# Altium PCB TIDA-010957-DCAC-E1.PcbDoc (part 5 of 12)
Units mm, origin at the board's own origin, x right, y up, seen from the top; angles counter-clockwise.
Board outline 300 x 300 mm, 4 copper layers (Top Layer, Layer 1, Layer 2, Bottom Layer), stack 1.787 mm thick; 1159 components, 619 nets, 3431 pads, 2942 vias.
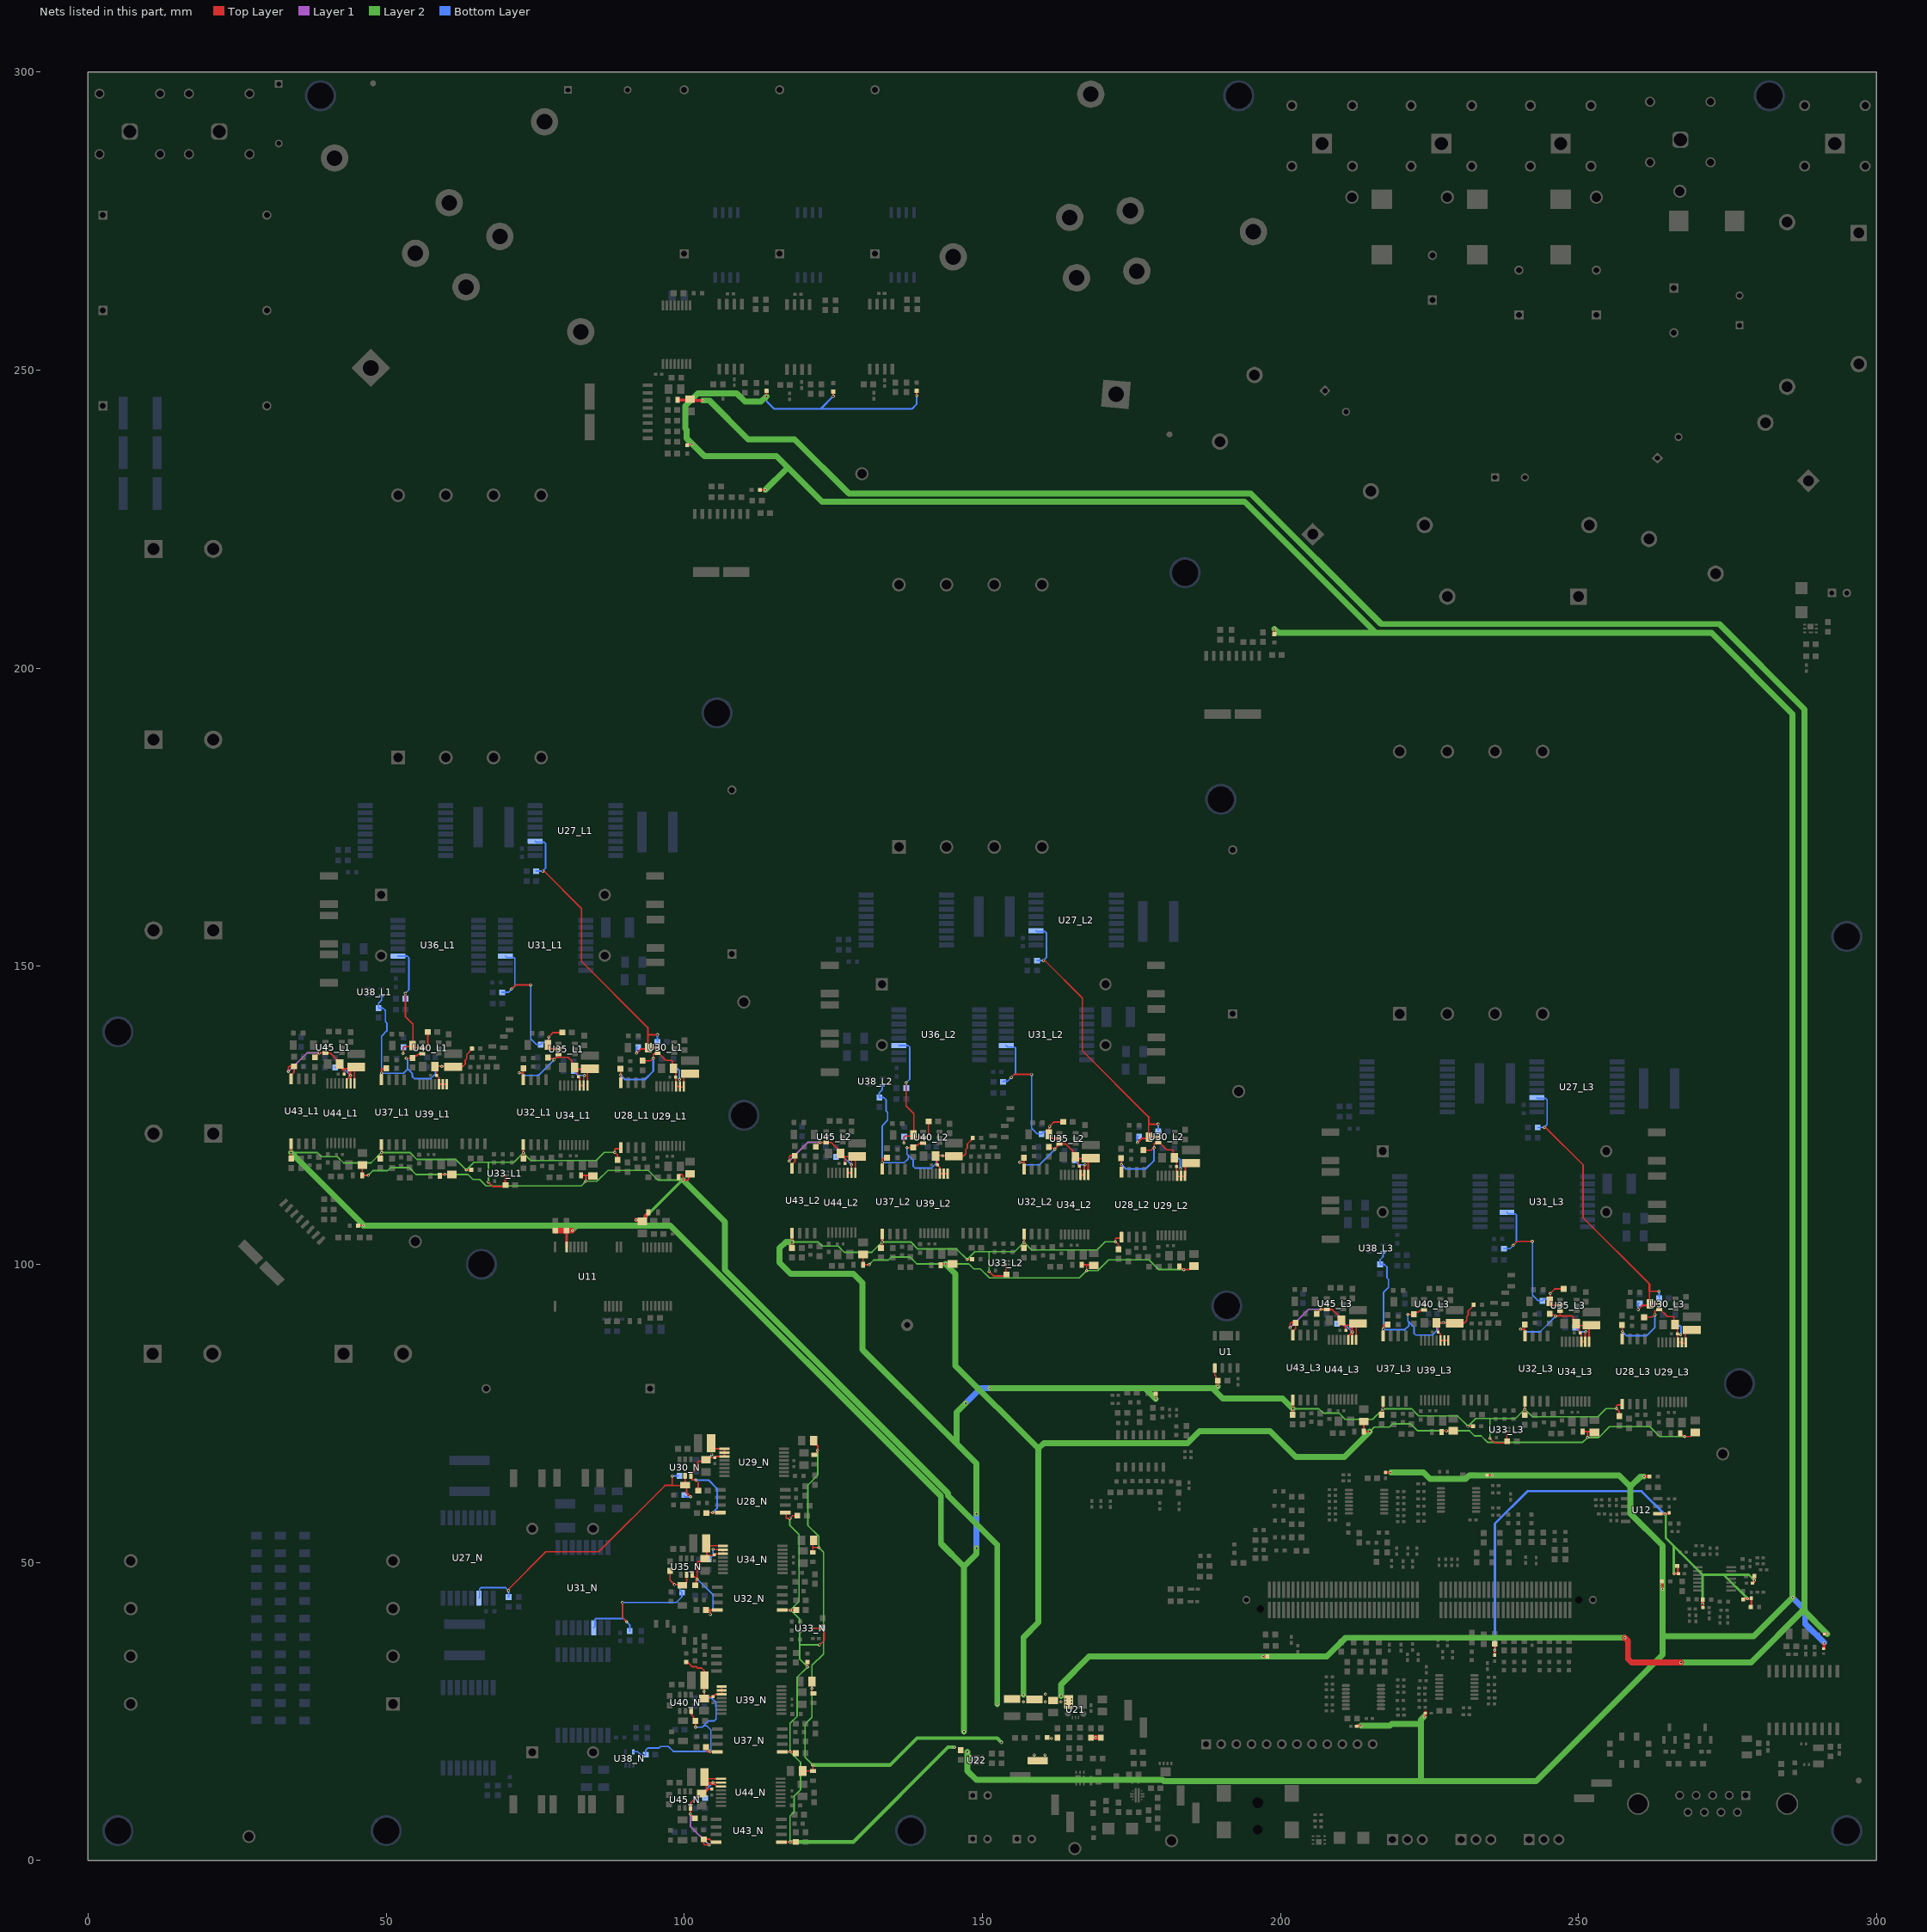
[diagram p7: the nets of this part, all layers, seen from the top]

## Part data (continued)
R290_L1 R290_L2 R290_L3 R290_N R301_L1 R301_L2 R301_L3 R301_N R311_L1 R311_L2 R311_L3 R311_N R328_L1 R328_L2 R328_L3 R328_N: library part CMP-0023259-5, "RES, 71.5 k, 1%, 0.1 W, 0603", Manufacturer=Yageo, Power_W=100mW, Supplier Part Number 1=311-71.5KHRCT-ND, TempCo="100 ppm/C", Tolerance_%=1%, Value2=0.1W, Value_Code=71k5, ValueDisplayed=71.5k
R312_L1 R312_L2 R312_L3 R312_N R313_L1 R313_L2 R313_L3 R313_N R314_L1 R314_L2 R314_L3 R314_N: library part CMP-0124370-1, "680 kOhms ±0.1% 0.2W, 1/5W Chip Resistor 0805 (2012 Metric) Anti-Sulfur, Automotive AEC-Q200, High Voltage, Moisture Resistant Thin Film", Digikey Part Number=541-TNPV0805680KBEEACT-ND, Manufacturer=Vishay, Mouser Part Number=71-TNPV0805680KBEEA, Operating Temperature Range="-55°C to +125°C", Power_W=200mW, TempCo=25ppm/°C, Tolerance_%=0.1%
R315_L1 R315_L2 R315_L3 R315_N: library part CMP-0122747-1, "8 kOhms ±0.1% 0.1W, 1/10W Chip Resistor 0603 (1608 Metric) Thin Film", Digikey Part Number=13-RT0603BRE078KLCT-ND, Manufacturer=Yageo, Mouser Part Number=603-RT0603BRE078KL, Operating Temperature Range="-55°C to +155°C", Power_W=100mW, TempCo=50ppm/°C, Tolerance_%=0.1%
R329: library part CMP-0026874-3, "RES, 200, 5%, 0.063 W, AEC-Q200 Grade 0, 0402", Manufacturer=Vishay-Dale, Power_W=63mW, Supplier Part Number 1=541-200JCT-ND, TempCo="200 ppm/C", Tolerance_%=5%, Value2=0.063W, Value_Code=200R, ValueDisplayed=200
RN1 RN2 RN3: library part CMP-0122946-1, "Automotive, 1700-V, Precision Resistive Divider", Manufacturer="Texas Instruments", Number Of Resistors=2, Operating Temperature Range="-40°C to +125°C", TempCo=1ppm/°C, Tolerance_%=0.05%
TP1: library part CMP-0055138-2, "Test Point, Miniature, Black, TH", Color=Black, Manufacturer="Keystone Electronics", Supplier Part Number 1=36-5001-ND
TP2 TP3 TP4 TP6 TP7 TP8 TP9 TP10 TP11 TP12 TP13: library part CMP-0055148-2, "Test Point, Multipurpose, Black, TH", Color=Black, Manufacturer="Keystone Electronics", Supplier Part Number 1=36-5011-ND
TP5: library part CMP-0055147-2, "Test Point, Multipurpose, Red, TH", Color=Red, Manufacturer="Keystone Electronics", Supplier Part Number 1=36-5010-ND
U1: library part CMP-0122473-1, "Automotive ±1.5°C, 3-kVRMS Isolated Temperature Sensor With Analog Output With < 2 Seconds Response Time and 500VRMS Working Voltage", Manufacturer="Texas Instruments", Max Supply Voltage=5.5V, Min Supply Voltage=2.3V, Operating Supply Current=10uA, Operating Temperature Range="-40°C to +150°C"
U2 U4 U5 U6: library part CMP-0097958-1, Manufacturer="Texas Instruments", Operating Temperature Range=to
U3: library part CMP-0121217-1, "Zero-Drift Amplifier 4 Circuit Rail-to-Rail 14-TSSOP", Digikey Part Number=296-OPA4388IPWRCT-ND, Input Bias Current=0.00003uA, Input Offset Voltage=0.00225mV, Manufacturer="Texas Instruments", Max Dual Supply Voltage=2.75V, Max Supply Voltage=5.5V, Min Dual Supply Voltage=1.25V, Min Supply Voltage=2.5V, Mouser Part Number=595-OPA4388IPWR, Nominal Supply Current=1.7-1.9mA, Operating Temperature Range="-40°C to +125°C", Output Current Per Channel=60mA, Voltage Gain=126dB
U7 U8 U9: library part CMP-0122725-1, "Automotive, Precision, ±1V Input Isolated Amplifiers With Single-Ended, Ratiometric Output", Input Bias Current=0.0035uA, Input Offset Voltage=0.4mV, Manufacturer="Texas Instruments", Max Supply Voltage=5.5V, Min Supply Voltage=3V, Operating Temperature Range="-40°C to +125°C", Output Current Per Channel=14mA
U10 U13: library part CMP-0123146-1, "Ultra-Small, 1.5W, 5.0V, 5kVRMS Isolation, Industrial DC/DC Module", Manufacturer="Texas Instruments", Max Supply Voltage=5.5V, Min Supply Voltage=4.5V, Nominal Supply Current=7-545mA, Operating Temperature Range="-40°C to +125°C", Output Voltage=5/5.5V, Switching Frequency=76MHz
U11: library part CMP-0044881-2, Manufacturer="Texas Instruments", Operating Temperature Range=to
U12: library part CMP-0121707-1, "Precision, Low-Offset-Voltage, Low-Noise, Low-Input-Bias-Current, Rail-to-Rail I/O, e-trim™ Operational Amplifiers", Digikey Part Number=296-OPA2392DRCT-ND, Input Bias Current=0.00000001uA, Input Offset Voltage=0.001mV, Manufacturer="Texas Instruments", Max Dual Supply Voltage=2.75V, Max Supply Voltage=5.5V, Min Dual Supply Voltage=850mV, Min Supply Voltage=1.7V, Mouser Part Number=595-OPA2392DR, Nominal Supply Current=1.22mA, Operating Temperature Range="-40°C to +125°C", Output Current Per Channel=65mA, Voltage Gain=132dB
U14: library part CMP-0097120-1, "Op Amp Quad Zero Drift Amplifier R-R I/O ±2.75V/5.5V 14-Pin SOIC T/R", Digikey Part Number=296-53511-1-ND, Input Bias Current=0.00003uA, Input Offset Voltage=0.00225mV, Manufacturer="Texas Instruments", Max Dual Supply Voltage=2.75V, Max Supply Voltage=5.5V, Min Dual Supply Voltage=1.25V, Min Supply Voltage=2.5V, Mouser Part Number=595-OPA4388IDR, Nominal Supply Current=1.7-1.9mA, Operating Temperature Range="-40°C to +125°C", Output Current Per Channel=60mA, Voltage Gain=148dB
U15 U16 U17 U18: library part CMP-0066280-1, "Quadruple Bus Buffer Gate with 3-State Outputs, PW0014A (TSSOP-14)", Alternate Manufacturer="Texas Instruments", Alternate PartNumber=SN74LVC126APW
U19: library part CMP-0088329-1, "2.7- 23V, 5.5 A, 28 mΩ Reverse Current Blocking eFuse with Input Reverse Polarity Protection", Manufacturer="Texas Instruments", Max Supply Voltage=23V, Min Supply Voltage=2.7V, Nominal Supply Current=0.5-6A, Operating Temperature Range="-40°C to +125°C", Output Voltage=42V, Threshold Voltage=1.2/1.1V
U20: library part CMP-0083940-3, "14 V Bidirectional Flat-Clamp Surge Protection Device, DRB0008A (VSON-8)", Alternate Manufacturer="Texas Instruments", Alternate PartNumber=TVS1401DRBT, Operating Temperature Range="-40 to 125 C"
U21: library part CMP-0034908-2, "3V to 16 V Input, 3-A Synchronous Step-Down Voltage Regulator Module, QFN-FCMOD7", Manufacturer="Texas Instruments", Max Supply Voltage=17V, Min Supply Voltage=3V, Nominal Supply Current=100-400uA, Operating Temperature Range="-40°C to +125°C", Output Voltage=0.6-10V, Switching Frequency=1.2MHz
U22: library part CMP-0013427-7, "500mA LDO, DRV0006A (WSON-6)", Alternate Manufacturer="Texas Instruments"
U23: library part CMP-0092023-2, "Reinforced 5-kVRMS Isolated CAN Transceiver with Integrated lowemissions DC-DC Converter", Manufacturer="Texas Instruments", Max Supply Voltage=5.5V, Min Supply Voltage=1.71V, Nominal Supply Current=0.3-124mA, Operating Temperature Range="-40°C to +105°C"
U24 U25: library part CMP-0120116-1, "±24 V Low Capacitance Surge Diode for Industrial Networks in SOT-23 Package", Breakdown Voltage=25.5V, Clamping Voltage=35V, Digikey Part Number=296-TSM24CADBZRCT-ND, Manufacturer="Texas Instruments", Mouser Part Number=595-TSM24CADBZR, Operating Temperature Range="-55°C to +150°C", ValueDisplayed=14pF
U27_L1 U27_L2 U27_L3 U27_N U31_L1 U31_L2 U31_L3 U31_N U36_L1 U36_L2 U36_L3 U36_N U42_L1 U42_L2 U42_L3 U42_N: library part CMP-0123798-1, Manufacturer="Texas Instruments", Operating Temperature Range=to
U28_L1 U28_L2 U28_L3 U28_N U32_L1 U32_L2 U32_L3 U32_N U37_L1 U37_L2 U37_L3 U37_N U43_L1 U43_L2 U43_L3 U43_N: library part CMP-0085676-1, "High Speed, Robust EMC Reinforced Dual-Channel Digital Isolator, DWV0008A (SOIC-8)", Alternate Manufacturer="Texas Instruments", Alternate PartNumber=ISO7721FDWVR, Operating Temperature Range="-55 to 125 C", Rating=Catalog
U29_L1 U29_L2 U29_L3 U29_N U34_L1 U34_L2 U34_L3 U34_N U39_L1 U39_L2 U39_L3 U39_N U44_L1 U44_L2 U44_L3 U44_N: library part CMP-0120108-2, "1.5W, High-Density, >5 kVRMS Isolated DC-DC Converter", Manufacturer="Texas Instruments", Max Supply Voltage=5.5V, Min Supply Voltage=4.5V, Operating Temperature Range="-40°C to +125°C", Output Voltage=5/5.5V
U30_L1 U30_L2 U30_L3 U30_N U35_L1 U35_L2 U35_L3 U35_N U40_L1 U40_L2 U40_L3 U40_N U45_L1 U45_L2 U45_L3 U45_N: library part CMP-0013231-2, "28-V Output Voltage Boost Converter with Power Diode and Isolation Switch, DBV0006A (SOT-6)", Alternate Manufacturer="Texas Instruments", Alternate PartNumber=TLV61046ADBVT
U33_L1 U33_L2 U33_L3 U33_N: library part CMP-0051217-4, "Single 3-Input Positive-AND Gate, DRY0006A (USON-6)", F @ Nom Voltage(Max)(Mhz)=150, Generic Part Number=SN74LVC1G11, ICC @ Nom Voltage(Max)(mA)=0.01, Manufacturer="Texas Instruments", Operating Temperature Range="-40 to 125 C", Operating Temperature Range(C)="-40 to 125,-40 to 85", Rating=Catalog, tpd @ Nom Voltage(Max)(ns)=20,7.8,6.2,4.6, Voltage(Nom)(V)=1.8,2.5,3.3,5
U38_L1 U38_L2 U38_L3 U38_N: library part CMP-0070963-2, "Micropower, 150mA Low-Dropout CMOS Voltage Regulator, 5-pin SC-70, Pb-Free", Manufacturer="Texas Instruments", PackageTopMarking=L5B*XTT, PowerWise=N
U41_L1 U41_L2 U41_L3 U41_N: library part CMP-0124047-1, "Precision, 2V Input, Basic and Reinforced Isolated Amplifiers With Fixed-Gain Differential Output", Input Bias Current=3.5nA, Input Offset Voltage=0.2mV, Manufacturer="Texas Instruments", Max Supply Voltage=5.5V, Min Supply Voltage=3V, Operating Temperature Range="-40°C to +125°C", Output Current Per Channel=11mA, Voltage Gain=1V/V
ZZ1: library part CMP-0003616-3
ZZ2: library part CMP-0077236-1
ZZ3: library part CMP-0077237-1
ZZ4: library part CMP-0077238-1

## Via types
v1: diameter 0.508, hole 0.254, Top Layer to Bottom Layer, tented both sides, 2942 vias

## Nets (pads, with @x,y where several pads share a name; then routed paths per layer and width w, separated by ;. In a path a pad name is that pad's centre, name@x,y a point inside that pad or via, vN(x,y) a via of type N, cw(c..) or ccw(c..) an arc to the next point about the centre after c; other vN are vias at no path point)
1V65: C5.1 C29.2 C35.2 C41.2 C48.2 C263.2 R38.1 R98.2 R106.2 R114.2 R122.2 R332.1 U12.6 | length 102.4
  Top Layer w0.2: R106.2@278.996,43.935 R106.2@278.996,43.985
  Top Layer w0.4: C263.2@235.925,34.45 v1(235.925,35.25) R38.1@235.925,36.35 ; U12.6@263.3,58.14 v1@264.5,58.14 ; v1(264.5,58.1) 264.529,58.1 264.637,58.208 265.15,58.208 265.2,58.258 R332.1@265.2,58.3 ; v1@266,48.1 v1(266.01,48.11) 266.019,48.119 266.725,48.119 266.675,48.169 266.675,49.275 C48.2@266.55,49.4 ; C29.2@270.849,43.726 270.826,43.576 270.826,42.45 270.876,42.4 R98.2@270.9,42.4 ; C35.2@277.617,43.782 277.767,43.932 277.998,43.932 278.001,43.935 v1(278.342,43.935) R106.2@278.996,43.935 ; C5.1@278.9,42.5 278.996,42.596 R106.2@278.996,43.985 ; R114.2@279.185,46.5 279.235,46.5 279.5,46.765 v1(279.5,46.994) C41.2@279.5,47.719
  Layer 2 w0.4: v1(264.5,58.1) 264.5,58.071 264.627,57.943 264.627,54.108 265.989,52.747 ; v1@265.989,48.13 265.989,52.747 ; v1(270.826,42.962) 270.826,47.91 ; v1(278.342,43.935) 274.367,47.91 ; v1(279.5,46.994) 278.584,47.91 274.367,47.91 ; 265.989,52.747 270.826,47.91 ; 270.826,47.91 274.367,47.91
  Bottom Layer w0.4: v1(235.925,35.25) 235.925,35.279 235.992,35.346 235.992,56.513 241.417,61.938 260.567,61.938 264.385,58.121 264.479,58.121 v1(264.5,58.1)
3V3: C13.1 C80.2 C81.1 C145.1 C186_L1.1 C186_L2.1 C186_L3.1 C186_N.1 C200_L1.1 C200_L2.1 C200_L3.1 C200_N.1 C223_L1.1 C223_L2.1 C223_L3.1 C223_N.1 C224_L1.1 C224_L2.1 C224_L3.1 C224_N.1 C243_L1.1 C243_L2.1 C243_L3.1 C243_N.1 FB2.1 FB3.1 FB4.1 FB5.1 FB6.1 FB7.2 FB8.2 FB9.2 FB11.1 FB13.1 FB14_L1.1 FB14_L2.1 FB14_L3.1 FB14_N.1 FB16.2 R164.2 R174.2 R175.2 R194.2 U1.1 U11.14 U22.1 U28_L1.1 U28_L2.1 U28_L3.1 U28_N.1 U32_L1.1 U32_L2.1 U32_L3.1 U32_N.1 U33_L1.5 U33_L2.5 U33_L3.5 U33_N.5 U37_L1.1 U37_L2.1 U37_L3.1 U37_N.1 U43_L1.1 U43_L2.1 U43_L3.1 U43_N.1 | length 1378.9
  Top Layer w0.2: FB6.1@45.3,106.5 v1(46.2,106.5) ; C145.1@146.35,18.477 C145.1@146.464,18.363 ; v1(179.1,77.4) FB11.1@179.1,78.3 ; U1.1@188.995,82.6 188.995,81.405 189.2,81.2 189.2,80.8 C13.1@189.5,80.5 v1(189.5,79.5) ; R175.2@212.8,22.5 R175.2@212.85,22.55 ; v1@213.45,22.55 v1(213.5,22.6) ; FB5.1@264,46.8 FB5.1@264.1,46.7 ; FB13.1@291.1,35.5 FB13.1@291.15,35.55 ; v1@291.15,36.45 v1(291.2,36.5)
  Top Layer w0.254: C243_L1.1@34.073,117.755 v1(34.073,118.755) U43_L1.1@34.073,120.226 ; C224_L1.1@49,117.755 49.224,117.979 v1(49.224,118.755) U37_L1.1@49.224,120.05 ; v1(63.45,115.817) 63.462,115.83 64.277,115.83 FB14_L1.1@64.289,115.842 ; v1(67.149,113.825) 67.942,113.032 69.954,113.032 69.956,113.029 U33_L1.5@69.956,114.967 ; C200_L1.1@73.005,117.708 v1(73.005,118.692) U32_L1.1@73.005,120.05 ; C186_L1.1@88.825,117.53 88.825,118.307 v1(88.35,118.782) 88.35,119.252 88.499,119.401 89.172,119.401 89.321,119.55 U28_L1.1@89.345,119.55 ; U43_N.1@116.274,3.073 v1(117.745,3.073) C243_N.1@118.745,3.073 ; U37_N.1@116.45,18.224 v1(117.745,18.224) 118.521,18.224 C224_N.1@118.745,18 ; U32_N.1@116.45,42.005 v1(117.808,42.005) C200_N.1@118.792,42.005 ; U28_N.1@116.95,58.345 116.95,58.321 117.099,58.172 117.099,57.499 117.248,57.35 v1(117.718,57.35) 118.193,57.825 C186_N.1@118.97,57.825 ; C243_L2.1@118.073,102.755 v1(118.073,103.755) U43_L2.1@118.073,105.226 ; FB14_N.1@120.658,33.289 120.67,33.277 120.67,32.463 v1(120.683,32.45) ; U33_N.5@121.533,38.956 123.471,38.956 123.471,36.944 v1(122.675,36.149) ; C224_L2.1@133,102.755 133.224,102.979 v1(133.224,103.755) U37_L2.1@133.224,105.05 ; v1(147.45,100.817) 147.462,100.83 148.277,100.83 FB14_L2.1@148.289,100.842 ; v1(151.149,98.825) 151.944,98.029 153.956,98.029 U33_L2.5@153.956,99.967 ; C200_L2.1@157.005,102.708 v1(157.005,103.692) U32_L2.1@157.005,105.05 ; C186_L2.1@172.825,102.53 172.825,103.307 v1(172.35,103.782) 172.35,104.252 172.499,104.401 173.172,104.401 173.321,104.55 U28_L2.1@173.345,104.55 ; C243_L3.1@202.073,74.755 v1(202.073,75.755) U43_L3.1@202.073,77.226 ; C224_L3.1@217,74.755 217.224,74.979 v1(217.224,75.755) U37_L3.1@217.224,77.05 ; v1(231.45,72.817) 231.462,72.83 232.277,72.83 FB14_L3.1@232.289,72.842 ; v1(235.149,70.825) 235.944,70.029 237.956,70.029 U33_L3.5@237.956,71.967 ; C200_L3.1@241.005,74.708 v1(241.005,75.692) U32_L3.1@241.005,77.05 ; C186_L3.1@256.825,74.53 256.825,75.307 v1(256.35,75.782) 256.35,76.252 256.499,76.401 257.172,76.401 257.321,76.55 U28_L3.1@257.345,76.55
  Top Layer w0.3: FB2.1@100.5,237.4 100.635,237.535 101.26,237.535 v1(101.3,237.575) ; FB3.1@112.7,229.9 v1(113.6,229.9) ; v1@113.7,245.6 113.8,245.7 FB9.2@113.8,246.5 ; FB8.2@125,246.4 v1(125,245.6) v1@125.1,245.5 ; v1(139,245.7) 139,246.4 FB7.2@139.1,246.5 ; FB4.1@199,205.7 v1(199,206.6)
  Top Layer w0.4: R174.2@217.6,65.1 v1(218.5,65.1) ; R164.2@234.8,64.6 v1(235.5,64.6)
  Top Layer w0.45: U11.14@80.279,102.904 C81.1@80.279,105.646
  Top Layer w0.5: R175.2@212.85,22.55 v1@213.45,22.55 ; v1(224.1,24.1) 224.1,24.102 224.292,24.294 224.292,24.9 R194.2@224.3,24.9 ; v1(261,64.4) FB16.2@261.9,64.4 ; v1(264.1,45.5) FB5.1@264.1,46.7 ; FB13.1@291.15,35.55 v1@291.15,36.45
  Top Layer w1: C80.2@78.375,105.65 v1@81.15,105.65
  Layer 2 w0.254: v1(34.073,118.755) 38.46,118.755 39.16,118.055 41.8,118.055 42.85,117.005 47.474,117.005 v1(49.224,118.755) 53.995,118.755 55.179,117.57 61.697,117.57 v1(63.45,115.817) 64.751,117.118 67.149,117.118 ; v1(67.149,113.825) 67.149,117.118 ; v1(88.35,118.782) 86.603,118.782 85.241,117.42 74.277,117.42 v1(73.005,118.692) 71.431,117.118 67.149,117.118 ; v1(117.718,57.35) 117.718,56.191 119.246,54.663 119.246,43.443 v1(117.808,42.005) 119.382,40.431 119.382,36.149 ; v1(117.745,3.073) 117.745,7.46 118.445,8.16 118.445,10.8 119.495,11.85 119.495,16.474 v1(117.745,18.224) 117.745,22.995 118.93,24.179 118.93,30.697 v1(120.683,32.45) 119.382,33.751 119.382,36.149 ; v1(118.073,103.755) 122.46,103.755 123.16,103.055 125.8,103.055 126.85,102.005 131.474,102.005 v1(133.224,103.755) 137.995,103.755 139.179,102.57 145.697,102.57 v1(147.45,100.817) 148.751,102.118 151.149,102.118 ; v1(122.675,36.149) 119.382,36.149 ; v1(151.149,98.825) 151.149,102.118 ; v1(172.35,103.782) 170.603,103.782 169.241,102.42 158.277,102.42 v1(157.005,103.692) 155.431,102.118 151.149,102.118 ; v1(202.073,75.755) 206.46,75.755 207.16,75.055 209.8,75.055 210.85,74.005 215.474,74.005 v1(217.224,75.755) 221.995,75.755 223.179,74.57 229.697,74.57 v1(231.45,72.817) 232.751,74.118 235.149,74.118 ; v1(235.149,70.825) 235.149,74.118 ; v1(256.35,75.782) 254.603,75.782 253.241,74.42 242.277,74.42 v1(241.005,75.692) 239.431,74.118 235.149,74.118
  Layer 2 w0.6: v1@81.352,105.65 82.2,106.498 ; v1@117.773,3.101 128.367,3.101 144.266,19 v1(145.3,19)
  Layer 2 w1: v1(34.073,118.755) 46.2,106.628 v1(46.2,106.5) ; v1(46.2,106.5) 82.2,106.498 97.646,106.498 143.054,61.09 143.054,53.147 146.901,49.3 ; v1(113.6,229.9) 117.035,233.335 ; v1(113.8,245.6) 112.9,244.7 110.2,244.7 108.8,246.1 102.3,246.1 100.216,244.016 100.216,240.17 100.413,239.973 100.413,238.558 103.394,235.577 115.473,235.577 123.123,227.926 193.974,227.926 216,205.9 ; v1(118.073,103.755) 117.055,103.755 116,102.7 116,100.3 117.884,98.416 128.384,98.416 129.9,96.9 129.9,85.673 145.687,69.887 ; v1(146.9,21.6) 146.901,21.601 146.901,49.3 ; v1(147.2,76.7) 145.687,75.187 145.687,69.887 ; v1(147.5,18.2) 147.5,15 149,13.5 180.229,13.5 180.429,13.3 223.6,13.3 ; v1(149,52.4) 149,51.399 146.901,49.3 ; v1(149,58.169) 149,66.573 145.687,69.887 ; v1(151.3,79.2) 177.3,79.2 ; v1(179.1,77.4) 177.3,79.2 ; v1(189.5,79.5) 189.2,79.2 188.6,79.2 ; v1(199,206.6) 199.7,205.9 216,205.9 ; v1(202.073,75.755) 200.351,77.477 190.323,77.477 188.6,79.2 ; v1(213.5,22.6) 218.4,22.6 218.7,22.9 223.6,22.9 ; v1@218.502,65.098 224.002,65.098 225.1,64 231.05,64 231.65,64.6 v1(235.5,64.6) 256.8,64.6 258.7,62.7 ; v1(224.1,24.1) 223.6,23.6 223.6,22.9 ; v1(261,64.4) 260.4,64.4 258.7,62.7 ; 177.3,79.2 188.6,79.2 ; 216,205.9 272.3,205.9 285.9,192.3 v1(285.9,44.1) 279.4,37.6 264.1,37.6 ; 223.6,13.3 242.9,13.3 264.1,34.5 264.1,37.6 ; 223.6,13.3 223.6,22.9 ; 258.7,62.7 258.7,58.2 264.1,52.8 v1(264.1,45.5) 264.1,37.6
  Bottom Layer w0.3: v1(113.8,245.6) 113.8,244.8 115.1,243.5 122.9,243.5 ; v1(125,245.6) 122.9,243.5 ; v1(139,245.7) 139,244.3 138.2,243.5 122.9,243.5
  Bottom Layer w1: v1(147.2,76.7) 149.7,79.2 v1(151.3,79.2) ; v1(149,52.4) v1(149,58.169) ; v1(285.9,44.1) 288.009,41.991 288.009,39.691 v1(291.2,36.5)
  other v1: 81.251,105.65
5V: C79.1 C93.1 C137.1 C139.1 C140.1 C143.1 C197_L1.1 C197_L2.1 C197_L3.1 C197_N.1 C220_L1.1 C220_L2.1 C220_L3.1 C220_N.1 C237_L1.1 C237_L2.1 C237_L3.1 C237_N.1 C254_L1.1 C254_L2.1 C254_L3.1 C254_N.1 D6.2 FB1.1 FB12.1 J18.1 L7.2 L9.2 L11_L1.2 L11_L2.2 L11_L3.2 L11_N.2 L13_L1.2 L13_L2.2 L13_L3.2 L13_N.2 L15_L1.2 L15_L2.2 L15_L3.2 L15_N.2 L17_L1.2 L17_L2.2 L17_L3.2 L17_N.2 R214.2 R218.2 U21.3 | length 1075.8
  Top Layer w0.2: C93.1@93.195,107.246 93.5,107.551 C93.1@93.533,107.584
  Top Layer w0.254: C254_L1.1@46,116.639 L17_L1.2@46,114.917 46.017,114.934 v1(47,114.934) ; L15_L1.2@59.01,115.142 59.088,115.064 v1(59.841,115.064) C237_L1.1@61,115.064 ; L13_L1.2@82.694,114.934 83.531,114.934 ; v1(83.517,113.934) 83.517,114.919 83.531,114.934 ; C220_L1.1@84.675,114.801 84.542,114.934 83.531,114.934 ; L11_L1.2@99.063,115.058 99.613,115.058 99.802,114.869 v1(99.802,114.108) 100.587,114.108 100.712,114.234 100.712,114.884 C197_L1.1@101,115.172 ; C254_N.1@119.861,15 L17_N.2@121.583,15 121.566,15.017 v1(121.566,16) ; C197_N.1@121.182,70.368 C197_N.1@121.469,70.08 ; L15_N.2@121.358,28.01 121.436,28.088 v1(121.436,28.841) C237_N.1@121.436,30 ; L11_N.2@121.442,68.063 121.474,68.095 122.024,68.095 122.215,68.286 122.215,68.557 122.392,68.734 v1(122.392,68.802) 122.392,69.563 122.243,69.712 C197_N.1@121.616,69.712 ; L13_N.2@121.566,51.694 121.566,52.531 ; C220_N.1@121.699,53.675 121.566,53.542 121.566,52.531 ; v1(122.566,52.517) 121.581,52.517 121.566,52.531 ; C254_L2.1@130,101.639 L17_L2.2@130,99.917 130.017,99.934 v1(131,99.934) ; L15_L2.2@143.01,100.142 143.088,100.064 v1(143.841,100.064) C237_L2.1@145,100.064 ; L13_L2.2@166.694,99.934 167.531,99.934 ; v1(167.517,98.934) 167.517,99.919 167.531,99.934 ; C220_L2.1@168.675,99.801 168.542,99.934 167.531,99.934 ; L11_L2.2@183.095,100.026 183.095,99.476 183.286,99.285 183.557,99.285 183.734,99.108 v1(183.802,99.108) 183.811,99.117 184.678,99.117 184.737,99.176 185.012,99.176 C197_L2.1@185.5,99.664 ; C197_L2.1@185,99.425 C197_L2.1@185,100.172 ; C254_L3.1@214,73.639 L17_L3.2@214,71.917 214.017,71.934 v1(215,71.934) ; L15_L3.2@227.01,72.142 227.088,72.064 v1(227.841,72.064) C237_L3.1@229,72.064 ; L13_L3.2@250.694,71.934 251.531,71.934 ; v1(251.517,70.934) 251.517,71.919 251.531,71.934 ; C220_L3.1@252.675,71.801 252.542,71.934 251.531,71.934 ; L11_L3.2@267.063,71.658 267.063,71.508 267.286,71.285 267.557,71.285 267.734,71.108 v1(267.802,71.108) 268.778,71.108 268.927,71.257 268.927,71.276 269.435,71.784 C197_L3.1@269.6,71.784
  Top Layer w0.4: v1(197.1,34.2) FB1.1@197.8,34.2
  Top Layer w0.5: L7.2@98.9,245 C79.1@101,245 ; C79.1@101,245.116 101.216,244.9 v1(103.1,244.9) ; FB12.1@291.2,38 v1(291.7,38)
  Top Layer w0.6: v1(91.909,107.452) 92.764,107.452 C93.1@93,107.216 ; C93.1@93.5,107.551 93.5,108.149 93.852,108.5 93.95,108.5 94,108.55 L9.2@94,108.7
  Top Layer w0.8: C137.1@168.207,20.596 R214.2@169.858,20.596
  Top Layer w1: v1(257.772,37.357) 258.3,36.83 258.3,33.786 258.886,33.2 v1(267.2,33.2)
  Layer 2 w0.254: v1(47,114.934) 47.768,115.702 50.261,115.702 50.782,116.223 53.865,116.223 55.024,115.064 v1(59.841,115.064) 63.721,115.064 64.568,114.217 65.662,114.217 66.735,113.144 82.727,113.144 v1(83.517,113.934) 85.376,113.934 87.202,115.761 93.986,115.761 95.638,114.108 99.799,114.108 v1(99.802,114.108) ; v1(121.566,16) 120.277,17.289 120.277,22.865 121.436,24.024 v1(121.436,28.841) 121.436,32.721 123.356,34.64 123.356,51.727 v1(122.566,52.517) 122.566,54.376 120.739,56.202 120.739,62.986 122.392,64.638 v1(122.392,68.802) ; v1(131,99.934) 131.768,100.702 134.261,100.702 134.782,101.223 137.865,101.223 139.024,100.064 v1(143.841,100.064) 147.721,100.064 148.568,99.217 149.662,99.217 151.179,97.7 166.283,97.7 v1(167.517,98.934) 169.376,98.934 171.202,100.761 177.986,100.761 179.638,99.108 v1(183.802,99.108) ; v1(215,71.934) 215.768,72.702 218.261,72.702 218.782,73.223 221.865,73.223 223.024,72.064 v1(227.841,72.064) 231.721,72.064 232.568,71.217 233.662,71.217 234.735,70.144 250.727,70.144 v1(251.517,70.934) 253.376,70.934 255.202,72.761 261.986,72.761 263.638,71.108 v1(267.802,71.108)
  Layer 2 w0.5: v1(91.909,107.452) 92.996,107.452 99.651,114.107 99.799,114.107 v1@99.799,114.108
  Layer 2 w0.6: v1(121.566,16) 134.533,16 139.033,20.5 152.5,20.5 v1(153.2,19.8)
  Layer 2 w1: v1(99.802,114.108) 106.8,107.111 106.8,99.041 144.254,61.587 144.254,61.218 152.5,52.972 v1(152.5,26.2) ; v1(103.1,244.9) 104.2,244.9 110.7,238.4 118.521,238.4 127.622,229.299 195.001,229.299 216.9,207.4 273.6,207.4 287.9,193.1 287.9,41.857 ; v1(143.841,100.064) 145.5,98.405 145.5,83 159.4,69.1 ; v1(156.9,27.8) 156.9,37.4 159.4,39.9 159.4,69.1 ; v1(163.2,27.6) 163.2,29.5 167.9,34.2 v1(197.1,34.2) 207.775,34.2 210.932,37.357 v1(257.772,37.357) ; v1(215,71.934) 210.766,67.7 202.6,67.7 198.267,72.033 186.433,72.033 184.4,70 160.3,70 159.4,69.1 ; v1(267.2,33.2) 278.94,33.2 287.72,41.98 v1(291.7,38)
  other v1: 158.7,17.7 160.5,17.7 161.6,20.5 169.047,20.633 163.983,26.069 164.983,26.069 163.983,26.569 164.983,26.569 156.9,26.6 160.6,26.6 163.2,26.6 163.983,27.069 164.983,27.069 160.6,27.9
5V_S1_GaN_L1: C187_L1.1 C193_L1.2 C194_L1.1 C195_L1.1 L10_L1.2 R286_L1.2 U28_L1.8 U29_L1.9 U29_L1.10 U29_L1.11 U30_L1.6 | length 28.6
  Top Layer w0.254: C187_L1.1@89.3,132.794 89.345,132.749 v1(89.345,131.722) U28_L1.8@89.345,130.45 ; C195_L1.1@93,134.148 94.348,134.148 94.744,134.545 v1(94.813,134.545) 94.813,135.246 95.389,135.246 U30_L1.6@95.538,135.395 95.738,135.395 96.914,134.219 97.863,134.219 98.012,134.07 98.012,133.061 C194_L1.1@98.204,132.869 98.588,132.485 C193_L1.2@98.588,131.367 98.588,130.748 98.669,130.667 98.669,129.828 98.696,129.855 U29_L1.10@99.275,129.855 ; U29_L1.10@99.397,129.75 U29_L1.9@99.872,129.75 ; U29_L1.9@99.925,129.855 99.925,131.463 100.445,131.982 L10_L1.2@101,131.982
  Bottom Layer w0.3: v1(89.345,131.722) 90.067,131 93.4,131 94.813,132.413 v1(94.813,134.545) 94.813,134.587 v1@94.8,134.6 ; R286_L1.2@98.1,132.8 98.2,132.7 99,132.7 99.2,132.5 v1(99.2,131)
5V_S1_GaN_L2: C187_L2.1 C193_L2.2 C194_L2.1 C195_L2.1 L10_L2.2 R286_L2.2 U28_L2.8 U29_L2.9 U29_L2.10 U29_L2.11 U30_L2.6 | length 28.9
  Top Layer w0.254: C187_L2.1@173.3,117.794 173.345,117.749 v1(173.345,116.722) U28_L2.8@173.345,115.45 ; C195_L2.1@177,119.148 178.348,119.148 178.744,119.545 v1(178.813,119.545) 178.813,120.246 179.389,120.246 U30_L2.6@179.538,120.395 179.738,120.395 180.914,119.219 181.863,119.219 182.012,119.07 182.012,118.061 C194_L2.1@182.204,117.869 182.588,117.485 C193_L2.2@182.588,116.367 182.588,115.748 182.669,115.667 182.669,114.828 182.747,114.75 183.397,114.75 184.047,114.75 184.047,116.409 184.62,116.982 L10_L2.2@185,116.982
  Bottom Layer w0.3: v1(173.345,116.722) 174.067,116 177.4,116 178.813,117.413 v1(178.813,119.545) 178.813,119.587 v1@178.8,119.6 ; R286_L2.2@182.1,117.8 182.2,117.7 183,117.7 183.2,117.5 v1(183.2,116)
5V_S1_GaN_L3: C187_L3.1 C193_L3.2 C194_L3.1 C195_L3.1 L10_L3.2 R286_L3.2 U28_L3.8 U29_L3.9 U29_L3.10 U29_L3.11 U30_L3.6 | length 28.7
  Top Layer w0.254: C187_L3.1@257.3,89.794 257.345,89.749 v1(257.345,88.722) U28_L3.8@257.345,87.45 ; C195_L3.1@261,91.148 262.348,91.148 262.744,91.545 v1(262.813,91.545) 262.813,92.246 263.389,92.246 U30_L3.6@263.538,92.395 263.738,92.395 264.914,91.219 265.863,91.219 266.012,91.07 266.012,90.061 C194_L3.1@266.204,89.869 266.588,89.485 C193_L3.2@266.588,88.367 266.588,87.748 266.669,87.667 266.669,86.828 266.741,86.9 U29_L3.10@267.325,86.9 ; U29_L3.10@267.325,86.75 267.872,86.75 267.872,88.409 268.445,88.982 L10_L3.2@269,88.982
  Bottom Layer w0.3: v1(257.345,88.722) 258.067,88 261.4,88 262.813,89.413 v1(262.813,91.545) 262.813,91.587 v1@262.8,91.6 ; R286_L3.2@266.1,89.8 266.2,89.7 267,89.7 267.191,89.509 267.191,88.291 v1(267.1,88.2)
5V_S1_GaN_N: C187_N.1 C193_N.2 C194_N.1 C195_N.1 L10_N.2 R286_N.2 U28_N.8 U29_N.9 U29_N.10 U29_N.11 U30_N.6 | length 27.4
  Top Layer w0.254: C195_N.1@102.352,62 102.352,63.348 101.955,63.744 v1(101.955,63.813) 101.254,63.813 101.254,64.389 U30_N.6@101.105,64.538 101.105,64.738 102.281,65.914 102.281,66.863 102.43,67.012 103.439,67.012 C194_N.1@103.631,67.204 104.015,67.588 C193_N.2@105.133,67.588 105.256,67.711 105.369,67.711 105.405,67.747 U29_N.11@106.75,67.747 U29_N.10@106.75,68.397 U29_N.9@106.75,69.047 105.091,69.047 104.518,69.62 L10_N.2@104.518,70 ; C187_N.1@103.706,58.3 103.751,58.345 v1(104.778,58.345) U28_N.8@106.05,58.345
  Bottom Layer w0.3: v1@101.9,63.8 101.913,63.813 v1(101.955,63.813) 104.087,63.813 105.5,62.4 105.5,59.067 v1(104.778,58.345) ; R286_N.2@103.7,67.1 103.7,67.248 103.981,67.529 104.129,67.529 v1@104.537,67.937
  other v1: 104.6,68.1
5V_S2_GaN_L1: C201_L1.1 C210_L1.2 C211_L1.1 C212_L1.1 L12_L1.2 R297_L1.2 U32_L1.8 U34_L1.9 U34_L1.10 U34_L1.11 U35_L1.6 | length 29.6
  Top Layer w0.254: v1(72.28,132.116) 73.005,132.116 ; U32_L1.8@73.005,130.95 73.005,132.116 ; C201_L1.1@73.005,132.866 73.005,132.116 ; C212_L1.1@77.155,134.671 77.326,134.5 77.922,134.5 78.106,134.316 v1(78.175,134.316) 78.559,134.7 80.525,134.7 81.144,134.082 81.144,133.196 C211_L1.1@81.616,132.723 ; 78.562,134.703 78.562,134.993 78.735,135.166 U35_L1.6@78.9,135.166 ; v1(83.244,131.672) 83.244,131.603 83.125,131.484 U34_L1.10@83.125,130 U34_L1.11@82.475,130 82.434,130.041 82.434,131.326 82.394,131.367 82.124,131.637 82.124,132.215 C211_L1.1@81.616,132.723 ; U34_L1.9@83.775,130 83.775,132.4 L12_L1.2@84.098,132.723 ; L12_L1.2@84.173,132.798 L12_L1.2@84.098,132.723 ; C211_L1.1@81.616,132.723 L12_L1.2@84.098,132.723
  Bottom Layer w0.254: v1(72.28,132.116) 72.797,132.116 73.242,131.672 75.546,131.672 78.175,134.301 v1(78.175,134.316) ; R297_L1.2@81.456,132.407 81.456,132.382 81.804,132.034 81.829,132.034 82.191,131.672 v1(83.244,131.672)
5V_S2_GaN_L2: C201_L2.1 C210_L2.2 C211_L2.1 C212_L2.1 L12_L2.2 R297_L2.2 U32_L2.8 U34_L2.9 U34_L2.10 U34_L2.11 U35_L2.6 | length 29.5
  Top Layer w0.254: v1(156.28,117.116) 157.005,117.116 ; U32_L2.8@157.005,115.95 157.005,117.116 ; C201_L2.1@157.005,117.866 157.005,117.116 ; C212_L2.1@161.155,119.671 161.326,119.5 161.922,119.5 162.106,119.316 v1(162.175,119.316) 162.559,119.7 ; 162.562,119.703 162.562,119.993 162.735,120.166 164.059,120.166 165.144,119.082 165.144,118.196 C211_L2.1@165.616,117.723 ; v1(167.244,116.672) 167.244,116.603 167.125,116.484 U34_L2.10@167.125,115 U34_L2.11@166.475,115 166.434,115.041 166.434,116.326 166.394,116.367 166.124,116.637 166.124,117.215 C211_L2.1@165.616,117.723 ; U34_L2.9@167.775,115 167.775,117.4 L12_L2.2@168.098,117.723 ; L12_L2.2@168.173,117.798 L12_L2.2@168.098,117.723 ; C211_L2.1@165.616,117.723 L12_L2.2@168.098,117.723
  Bottom Layer w0.254: v1(156.28,117.116) 156.797,117.116 157.242,116.672 159.546,116.672 162.175,119.301 v1(162.175,119.316) ; R297_L2.2@165.456,117.407 165.456,117.382 165.804,117.034 165.829,117.034 166.191,116.672 v1(167.244,116.672)
5V_S2_GaN_L3: C201_L3.1 C210_L3.2 C211_L3.1 C212_L3.1 L12_L3.2 R297_L3.2 U32_L3.8 U34_L3.9 U34_L3.10 U34_L3.11 U35_L3.6 | length 29.5
  Top Layer w0.254: v1(240.28,89.116) 241.005,89.116 ; U32_L3.8@241.005,87.95 241.005,89.116 ; C201_L3.1@241.005,89.866 241.005,89.116 ; C212_L3.1@245.155,91.671 245.326,91.5 245.922,91.5 246.106,91.316 v1(246.175,91.316) 246.888,91.316 ; U35_L3.6@246.891,92.166 246.891,91.319 246.888,91.316 ; v1(251.244,88.672) 251.244,88.603 251.125,88.484 U34_L3.10@251.125,87 U34_L3.11@250.475,87 250.434,87.041 250.434,88.326 250.394,88.367 250.124,88.637 250.124,89.215 C211_L3.1@249.616,89.723 ; U34_L3.9@251.775,87 251.775,89.4 L12_L3.2@252.098,89.723 ; L12_L3.2@252.173,89.798 L12_L3.2@252.098,89.723 ; 246.888,91.316 248.909,91.316 249.144,91.082 249.144,90.196 C211_L3.1@249.616,89.723 ; C211_L3.1@249.616,89.723 L12_L3.2@252.098,89.723
  Bottom Layer w0.254: v1(240.28,89.116) 240.797,89.116 241.242,88.672 243.546,88.672 246.175,91.301 v1(246.175,91.316) ; R297_L3.2@249.456,89.407 249.456,89.382 249.804,89.034 249.829,89.034 250.191,88.672 v1(251.244,88.672)
5V_S2_GaN_N: C201_N.1 C210_N.2 C211_N.1 C212_N.1 L12_N.2 R297_N.2 U32_N.8 U34_N.9 U34_N.10 U34_N.11 U35_N.6 | length 29.9
  Top Layer w0.254: U35_N.6@101.334,47.9 101.334,47.735 101.507,47.562 101.797,47.562 ; 101.8,47.559 v1(102.184,47.175) ; C212_N.1@101.829,46.155 102,46.326 102,46.922 102.184,47.106 v1(102.184,47.175) ; C201_N.1@103.634,42.005 104.384,42.005 ; L12_N.2@103.702,53.173 L12_N.2@103.777,53.098 ; v1(104.384,41.28) 104.384,42.005 ; v1(104.828,52.244) 104.897,52.244 105.016,52.125 U34_N.10@106.5,52.125 U34_N.11@106.5,51.475 106.459,51.434 105.174,51.434 105.133,51.394 104.863,51.124 104.285,51.124 C211_N.1@103.777,50.616 ; U32_N.8@105.55,42.005 104.384,42.005 ; U34_N.9@106.5,52.775 104.1,52.775 L12_N.2@103.777,53.098 ; v1(102.184,47.175) 102.184,49.909 102.418,50.144 103.304,50.144 C211_N.1@103.777,50.616 ; C211_N.1@103.777,50.616 L12_N.2@103.777,53.098
  Bottom Layer w0.254: v1(102.184,47.175) 102.199,47.175 104.828,44.546 104.828,42.242 104.384,41.797 v1(104.384,41.28) ; R297_N.2@104.093,50.456 104.118,50.456 104.466,50.804 104.466,50.829 104.828,51.191 v1(104.828,52.244)
5V_S3_GaN_L1: C225_L1.1 C228_L1.1 C233_L1.2 C234_L1.1 C235_L1.1 FB15_L1.2 L14_L1.2 R307_L1.2 U37_L1.8 U38_L1.5 U39_L1.9 U39_L1.10 U39_L1.11 U40_L1.6 | length 47.5
  Top Layer w0.254: v1(53.372,134.582) 54.363,134.582 C235_L1.1@54.404,134.623 54.729,134.948 55.085,134.948 55.376,135.238 55.988,135.238 U40_L1.6@56.083,135.333 ; U39_L1.9@60.16,130.208 U39_L1.10@59.51,130.208 U39_L1.11@58.86,130.208 58.86,131.254 C233_L1.2@58.458,131.657 58.458,132.898 C234_L1.1@58.174,133.182 v1(59.333,133.182) 61.159,133.182 L14_L1.2@61.225,133.116 62.798,133.116 63.257,133.575 63.257,134.245 63.5,134.488 63.5,135.184 FB15_L1.2@64.3,135.984
  Top Layer w0.3: U37_L1.8@49.224,130.95 v1(49.224,132.076) 49.224,132.624 49.4,132.8 C225_L1.1@49.8,132.8
  Bottom Layer w0.254: U38_L1.5@49.203,145.025 49.232,144.995 49.232,144.355 49.262,144.325 48.723,143.786 C228_L1.1@48.723,142.975 49.448,142.975 49.876,142.547 49.876,140.711 50.123,140.464 50.123,139.155 49.224,138.256 v1(49.224,132.076) ; v1@49.283,132.039 52.89,132.039 53.617,132.766 ; v1(53.372,134.582) 53.372,134.552 53.599,134.325 ; 53.617,134.307 53.617,132.766 ; v1(59.333,133.182) 58.333,133.182 R307_L1.2@58.258,133.107 58.258,131.924 57.476,131.142 54.701,131.142 54.404,131.439 54.404,131.979 53.617,132.766
  Bottom Layer w0.3: v1(49.224,132.076) v1@49.283,132.135
5V_S3_GaN_L2: C225_L2.1 C228_L2.1 C233_L2.2 C234_L2.1 C235_L2.1 FB15_L2.2 L14_L2.2 R307_L2.2 U37_L2.8 U38_L2.5 U39_L2.9 U39_L2.10 U39_L2.11 U40_L2.6 | length 47.8
  Top Layer w0.254: v1(137.372,119.582) 138.363,119.582 138.729,119.948 139.085,119.948 139.376,120.238 139.988,120.238 U40_L2.6@140.083,120.333 ; U39_L2.9@144.16,115.208 U39_L2.10@143.51,115.208 U39_L2.11@142.86,115.208 142.86,116.254 C233_L2.2@142.458,116.657 142.458,117.898 C234_L2.1@142.174,118.182 v1(143.333,118.182) 145.159,118.182 L14_L2.2@145.225,118.116 146.798,118.116 147.257,118.575 147.257,119.245 147.5,119.488 147.5,120.184 FB15_L2.2@148.3,120.984
  Top Layer w0.3: U37_L2.8@133.224,115.95 v1(133.224,117.076) 133.224,117.624 133.4,117.8 C225_L2.1@133.8,117.8
  Bottom Layer w0.254: U38_L2.5@133.203,130.025 133.232,129.995 133.232,129.355 133.262,129.325 132.723,128.786 C228_L2.1@132.723,127.975 133.448,127.975 133.876,127.547 133.876,125.711 134.123,125.464 134.123,124.155 133.224,123.256 v1(133.224,117.076) ; v1@133.341,117.039 136.89,117.039 137.567,117.716 137.567,118.197 ; v1(137.372,119.582) 137.372,118.493 138.404,117.46 138.404,116.439 138.701,116.142 141.476,116.142 142.258,116.924 R307_L2.2@142.258,118.107 142.333,118.182 v1(143.333,118.182)
  Bottom Layer w0.3: v1(133.224,117.076) v1@133.264,117.116
5V_S3_GaN_L3: C225_L3.1 C228_L3.1 C233_L3.2 C234_L3.1 C235_L3.1 FB15_L3.2 L14_L3.2 R307_L3.2 U37_L3.8 U38_L3.5 U39_L3.9 U39_L3.10 U39_L3.11 U40_L3.6 | length 47.9
  Top Layer w0.254: v1(221.372,91.582) 222.363,91.582 C235_L3.1@222.404,91.623 222.729,91.948 223.085,91.948 223.376,92.238 223.988,92.238 U40_L3.6@224.083,92.333 ; U39_L3.9@228.16,87.208 U39_L3.10@227.51,87.208 U39_L3.11@226.86,87.208 226.86,88.254 C233_L3.2@226.458,88.657 226.458,89.898 C234_L3.1@226.174,90.182 v1(227.333,90.182) 229.159,90.182 L14_L3.2@229.225,90.116 230.798,90.116 231.257,90.575 231.257,91.245 231.5,91.488 231.5,92.184 FB15_L3.2@232.3,92.984
  Top Layer w0.3: U37_L3.8@217.224,87.95 v1@217.224,89.076 ; v1@217.315,89.076 v1@217.224,89.076 ; C225_L3.1@217.8,89.8 217.4,89.8 217.224,89.624 v1@217.224,89.076
  Bottom Layer w0.254: U38_L3.5@217.203,102.025 217.232,101.995 217.232,101.355 217.262,101.325 216.723,100.786 C228_L3.1@216.723,99.975 217.448,99.975 217.876,99.547 217.876,97.711 218.123,97.464 218.123,96.155 217.311,95.344 217.311,89.068 217.511,89.068 217.539,89.039 220.89,89.039 221.567,89.716 221.567,90.197 ; v1(221.372,91.582) 221.372,90.493 222.404,89.46 222.404,88.439 222.701,88.142 225.476,88.142 226.258,88.924 R307_L3.2@226.258,90.107 226.333,90.182 v1(227.333,90.182)
  other v1: 217.283,89.116
5V_S3_GaN_N: C225_N.1 C228_N.1 C233_N.2 C234_N.1 C235_N.1 FB15_N.2 L14_N.2 R307_N.2 U37_N.8 U38_N.5 U39_N.9 U39_N.10 U39_N.11 U40_N.6 | length 48
  Top Layer w0.254: FB15_N.2@100.516,33.3 101.316,32.5 102.012,32.5 102.255,32.257 102.925,32.257 103.384,31.798 L14_N.2@103.384,30.225 103.318,30.159 v1(103.318,28.333) C234_N.1@103.318,27.174 103.602,27.458 C233_N.2@104.843,27.458 105.246,27.86 U39_N.11@106.292,27.86 U39_N.10@106.292,28.51 U39_N.9@106.292,29.16 ; U40_N.6@101.167,25.083 101.262,24.988 101.262,24.376 101.552,24.085 101.552,23.729 C235_N.1@101.877,23.404 101.918,23.363 v1(101.918,22.372)
  Top Layer w0.3: C225_N.1@103.7,18.8 103.7,18.4 103.876,18.224 U37_N.8@105.55,18.224 ; v1@104.424,18.224 v1@104.424,18.315
  Bottom Layer w0.254: U38_N.5@91.475,18.203 91.505,18.232 92.145,18.232 92.175,18.262 92.714,17.723 C228_N.1@93.525,17.723 93.525,18.448 93.953,18.876 95.789,18.876 96.036,19.123 97.345,19.123 98.185,18.283 103.751,18.283 ; v1(101.918,22.372) 103.007,22.372 104.04,23.404 105.061,23.404 105.358,23.701 105.358,25.748 105.318,25.788 105.318,26.516 104.576,27.258 R307_N.2@103.393,27.258 103.318,27.333 v1(103.318,28.333) ; 103.303,22.567 103.784,22.567 104.461,21.89 104.461,18.591 104.406,18.536 104.406,18.33 v1@104.453,18.283
  Bottom Layer w0.3: 103.751,18.283 103.9,18.283 v1@104.453,18.283
  other v1: 104.357,18.315
5V_S4_GaN_L1: C244_L1.1 C250_L1.2 C251_L1.1 C252_L1.1 L16_L1.2 R324_L1.2 U43_L1.8 U44_L1.9 U44_L1.10 U44_L1.11 U45_L1.6 | length 31
  Top Layer w0.254: v1(33.598,132.334) 33.598,133.009 33.836,133.246 34.513,133.246 C252_L1.1@34.561,133.198 34.561,132.214 34.073,131.726 U43_L1.8@34.073,131.126 ; C244_L1.1@38.076,134.707 38.424,135.055 38.424,135.182 38.651,135.409 38.752,135.409 v1(38.801,135.457) 39.377,135.457 39.488,135.347 U45_L1.6@39.727,135.347 ; U45_L1.6@39.801,135.434 40.677,135.434 41.738,134.373 41.738,133.755 C251_L1.1@42.219,133.273 ; C250_L1.2@42.956,131.907 42.956,132.451 42.807,132.6 42.727,132.6 42.219,133.108 C251_L1.1@42.219,133.273 ; U44_L1.11@43.404,130.338 43.404,130.983 43.77,131.349 43.77,132.218 L16_L1.2@44.054,132.502 ; U44_L1.10@44.054,130.338 v1(44.054,131.657) L16_L1.2@44.054,132.502 ; U44_L1.9@44.704,130.338 44.704,132.502 L16_L1.2@44.994,132.791 ; C251_L1.1@42.219,133.273 42.701,132.791 44.343,132.791 L16_L1.2@44.054,132.502
  Layer 1 w0.254: v1(33.598,132.334) 36.722,135.457 v1(38.801,135.457)
  Bottom Layer w0.254: R324_L1.2@41.476,133.023 42.688,133.023 v1(44.054,131.657)
5V_S4_GaN_L2: C244_L2.1 C250_L2.2 C251_L2.1 C252_L2.1 L16_L2.2 R324_L2.2 U43_L2.8 U44_L2.9 U44_L2.10 U44_L2.11 U45_L2.6 | length 30.1
  Top Layer w0.254: v1(117.598,117.334) 117.598,118.009 117.836,118.246 118.513,118.246 C252_L2.1@118.561,118.198 118.561,117.214 118.073,116.726 U43_L2.8@118.073,116.126 ; C244_L2.1@122.076,119.707 122.424,120.055 122.424,120.182 122.651,120.409 122.752,120.409 v1(122.801,120.457) 122.824,120.434 124.677,120.434 125.738,119.373 125.738,118.755 125.903,118.755 126.219,118.438 C251_L2.1@126.219,118.573 ; C251_L2.1@126.219,118.273 C251_L2.1@126.538,117.955 ; C250_L2.2@126.956,116.907 126.956,117.702 126.758,117.9 126.727,117.9 126.621,118.007 126.621,118.037 128.939,118.037 L16_L2.2@128.994,118.091 ; U44_L2.11@127.404,115.338 127.976,115.338 128.054,115.416 U44_L2.10@128.054,115.988 ; U44_L2.10@128.054,115.338 U44_L2.10@128.054,115.988 ; v1@128.054,116.633 128.054,117.518 L16_L2.2@128.327,117.791 ; v1(128.054,116.657) U44_L2.10@128.054,115.988 ; U44_L2.9@128.704,115.338 128.704,117.502 L16_L2.2@128.994,117.791
  Layer 1 w0.254: v1(117.598,117.334) 120.722,120.457 v1(122.801,120.457)
  Bottom Layer w0.254: R324_L2.2@125.476,118.023 126.688,118.023 v1(128.054,116.657)
5V_S4_GaN_L3: C244_L3.1 C250_L3.2 C251_L3.1 C252_L3.1 L16_L3.2 R324_L3.2 U43_L3.8 U44_L3.9 U44_L3.10 U44_L3.11 U45_L3.6 | length 31.1
  Top Layer w0.254: v1(201.598,89.334) 201.598,90.009 201.836,90.246 202.513,90.246 C252_L3.1@202.561,90.198 202.561,89.214 202.073,88.726 U43_L3.8@202.073,88.126 ; C244_L3.1@206.076,91.707 206.424,92.055 206.424,92.182 206.651,92.409 206.752,92.409 v1(206.801,92.457) 206.849,92.409 207.008,92.409 207.014,92.403 207.659,92.403 208.708,92.403 209.738,91.373 209.738,90.755 C251_L3.1@210.219,90.273 ; C250_L3.2@210.956,88.907 210.956,89.451 210.807,89.6 210.727,89.6 210.219,90.108 C251_L3.1@210.219,90.273 ; U44_L3.11@211.404,87.338 211.404,87.983 211.77,88.349 211.77,89.218 L16_L3.2@212.054,89.502 ; U44_L3.10@212.054,87.338 v1(212.054,88.657) L16_L3.2@212.054,89.502 ; U44_L3.9@212.704,87.338 212.704,89.502 L16_L3.2@212.994,89.791 ; C251_L3.1@210.219,90.273 210.701,89.791 212.343,89.791 L16_L3.2@212.054,89.502
  Layer 1 w0.254: v1(201.598,89.334) 204.722,92.457 v1(206.801,92.457)
  Bottom Layer w0.254: R324_L3.2@209.476,90.023 210.688,90.023 v1(212.054,88.657)
5V_S4_GaN_N: C244_N.1 C250_N.2 C251_N.1 C252_N.1 L16_N.2 R324_N.2 U43_N.8 U44_N.9 U44_N.10 U44_N.11 U45_N.6 | length 31
  Top Layer w0.254: U45_N.6@101.066,8.801 101.066,9.677 102.127,10.738 102.745,10.738 C251_N.1@103.227,11.219 ; U45_N.6@101.127,8.726 101.127,8.462 101.043,8.377 v1(101.043,7.801) 101.091,7.752 101.091,7.651 101.318,7.424 101.445,7.424 C244_N.1@101.793,7.076 ; L16_N.2@103.709,13.994 103.998,13.704 U44_N.9@106.162,13.704 ; v1(104.166,2.598) 103.491,2.598 103.254,2.836 103.254,3.513 C252_N.1@103.302,3.561 104.286,3.561 104.774,3.073 U43_N.8@105.374,3.073 ; C250_N.2@104.593,11.956 104.049,11.956 103.9,11.807 103.9,11.727 103.392,11.219 C251_N.1@103.227,11.219 ; U44_N.11@106.162,12.404 105.517,12.404 105.151,12.77 104.282,12.77 L16_N.2@103.998,13.054 ; U44_N.10@106.162,13.054 v1(104.843,13.054) L16_N.2@103.998,13.054 ; C251_N.1@103.227,11.219 103.709,11.701 103.709,13.343 L16_N.2@103.998,13.054
  Layer 1 w0.254: v1(101.043,7.801) 101.043,5.722 v1(104.166,2.598)
  Bottom Layer w0.254: R324_N.2@103.477,10.476 103.477,11.688 v1(104.843,13.054)
10V_S1_GaN_L1: C190_L1.1 C192_L1.1 R285_L1.2 R289_L1.2 U27_L1.11 U30_L1.5 | length 52.6
  Top Layer w0.25: 93.9,138.5 v1(95.5,138.5)
  Top Layer w0.254: v1(76.253,165.957) 76.302,165.908 76.549,165.908 82.766,159.691 82.766,150.834 93.9,139.7 ; 93.9,138.5 93.9,136.42 C192_L1.1@93.975,136.345 U30_L1.5@95.538,136.345
  Top Layer w0.3: v1(92,135.4) 92.7,136.1 93.9,136.1 C192_L1.1@94,136 ; 93.9,138.5 93.9,139.7
  Bottom Layer w0.254: U27_L1.11@75,170.95 75.127,170.823 76.504,170.823 76.75,170.577 76.75,166.453 v1(76.253,165.957) C190_L1.1@75.151,165.957
  Bottom Layer w0.3: v1(92,135.4) 92,136.4 R285_L1.2@92.1,136.5 ; R289_L1.2@95.5,137.5 v1(95.5,138.5)
10V_S1_GaN_L2: C190_L2.1 C192_L2.1 R285_L2.2 R289_L2.2 U27_L2.11 U30_L2.5 | length 52.6
  Top Layer w0.25: 177.9,123.5 v1(179.5,123.5)
  Top Layer w0.254: v1(160.253,150.957) 160.302,150.908 160.549,150.908 166.766,144.691 166.766,135.834 177.9,124.7 ; 177.9,123.5 177.9,121.42 C192_L2.1@177.975,121.345 U30_L2.5@179.538,121.345
  Top Layer w0.3: v1(176,120.4) 176.7,121.1 177.9,121.1 C192_L2.1@178,121 ; 177.9,123.5 177.9,124.7
  Bottom Layer w0.254: U27_L2.11@159,155.95 159.127,155.823 160.504,155.823 160.75,155.577 160.75,151.453 v1(160.253,150.957) C190_L2.1@159.151,150.957
  Bottom Layer w0.3: v1(176,120.4) 176,121.4 R285_L2.2@176.1,121.5 ; R289_L2.2@179.5,122.5 v1(179.5,123.5)
10V_S1_GaN_L3: C190_L3.1 C192_L3.1 R285_L3.2 R289_L3.2 U27_L3.11 U30_L3.5 | length 52.6
  Top Layer w0.25: 261.9,95.5 v1(263.5,95.5)
  Top Layer w0.254: v1(244.253,122.957) 244.302,122.908 244.549,122.908 250.766,116.691 250.766,107.834 261.9,96.7 ; 261.9,95.5 261.9,93.42 C192_L3.1@261.975,93.345 U30_L3.5@263.538,93.345
  Top Layer w0.3: v1(260,92.4) 260.7,93.1 261.9,93.1 C192_L3.1@262,93 ; 261.9,95.5 261.9,96.7
  Bottom Layer w0.254: U27_L3.11@243,127.95 243.127,127.823 244.504,127.823 244.75,127.577 244.75,123.453 v1(244.253,122.957) C190_L3.1@243.151,122.957
  Bottom Layer w0.3: v1(260,92.4) 260,93.4 R285_L3.2@260.1,93.5 ; R289_L3.2@263.5,94.5 v1(263.5,95.5)
10V_S1_GaN_N: C190_N.1 C192_N.1 R285_N.2 R289_N.2 U27_N.11 U30_N.5 | length 52.6
  Top Layer w0.25: 98,62.9 v1(98,64.5)
  Top Layer w0.254: v1(70.543,45.253) 70.592,45.302 70.592,45.549 76.809,51.766 85.666,51.766 96.8,62.9 ; 98,62.9 100.08,62.9 C192_N.1@100.155,62.975 U30_N.5@100.155,64.538
  Top Layer w0.3: 96.8,62.9 98,62.9 ; C192_N.1@100.5,63 100.4,62.9 100.4,61.7 v1(101.1,61)
  Bottom Layer w0.254: U27_N.11@65.55,44 65.677,44.127 65.677,45.504 65.923,45.75 70.047,45.75 v1(70.543,45.253) C190_N.1@70.543,44.151
  Bottom Layer w0.3: v1(98,64.5) R289_N.2@99,64.5 ; R285_N.2@100,61.1 100.1,61 v1(101.1,61)
10V_S2_GaN_L1: C204_L1.1 C208_L1.1 R296_L1.2 R300_L1.2 U31_L1.11 U35_L1.5 | length 31.8
  Top Layer w0.254: v1(71.038,146.164) 71.724,146.85 v1(74.25,146.85) ; U35_L1.5@78.9,136.116 77.59,136.116 77.155,136.55 C208_L1.1@77.155,136.8 77.275,136.92 v1(77.275,138.132) 78.018,138.875 R300_L1.2@79.544,138.875
  Bottom Layer w0.254: C204_L1.1@69.482,145.625 70.499,145.625 71.577,146.703 71.577,151.303 71.428,151.452 70.248,151.452 U31_L1.11@70,151.7 ; v1(74.25,146.85) 74.275,146.825 74.275,137.833 75.223,136.885 75.927,136.885 R296_L1.2@75.93,136.882 ; R296_L1.2@75.93,136.857 R296_L1.2@75.93,136.882 ; v1(77.275,138.132) 77.226,138.084 77.226,137.581 76.875,137.23 76.278,137.23 R296_L1.2@75.93,136.882
10V_S2_GaN_L2: C204_L2.1 C208_L2.1 R296_L2.2 R300_L2.2 U31_L2.11 U35_L2.5 | length 31.7
  Top Layer w0.254: v1(154.849,131.351) 155.348,131.85 v1(158.25,131.85) ; U35_L2.5@162.9,121.116 161.59,121.116 161.155,121.55 C208_L2.1@161.155,121.8 161.275,121.92 v1(161.275,123.132) 162.018,123.875 R300_L2.2@163.544,123.875
  Bottom Layer w0.254: C204_L2.1@153.482,130.625 153.573,130.716 154.214,130.716 v1(154.849,131.351) 155.577,132.079 155.577,136.303 155.428,136.452 154.248,136.452 U31_L2.11@154,136.7 ; v1(158.25,131.85) 158.275,131.825 158.275,122.833 159.223,121.885 159.927,121.885 R296_L2.2@159.93,121.882 ; R296_L2.2@159.93,121.857 R296_L2.2@159.93,121.882 ; v1(161.275,123.132) 161.226,123.084 161.226,122.581 160.875,122.23 160.278,122.23 R296_L2.2@159.93,121.882
10V_S2_GaN_L3: C204_L3.1 C208_L3.1 R296_L3.2 R300_L3.2 U31_L3.11 U35_L3.5 | length 31.8
  Top Layer w0.254: v1(239.038,103.164) 239.724,103.85 v1(242.25,103.85) ; U35_L3.5@246.9,93.116 245.59,93.116 245.155,93.55 C208_L3.1@245.155,93.8 245.275,93.92 v1(245.275,95.132) 246.018,95.875 R300_L3.2@247.544,95.875
  Bottom Layer w0.254: C204_L3.1@237.482,102.625 238.499,102.625 239.577,103.703 239.577,108.303 239.428,108.452 238.248,108.452 U31_L3.11@238,108.7 ; v1(242.25,103.85) 242.275,103.825 242.275,94.833 243.223,93.885 243.927,93.885 R296_L3.2@243.93,93.882 ; R296_L3.2@243.93,93.857 R296_L3.2@243.93,93.882 ; v1(245.275,95.132) 245.226,95.084 245.226,94.581 244.875,94.23 244.278,94.23 R296_L3.2@243.93,93.882
10V_S2_GaN_N: C204_N.1 C208_N.1 R296_N.2 R300_N.2 U31_N.11 U35_N.5 | length 31.8
  Top Layer w0.254: v1(89.65,43.25) 89.65,40.724 v1(90.336,40.038) ; R300_N.2@97.625,48.544 97.625,47.018 v1(98.368,46.275) 99.58,46.275 C208_N.1@99.7,46.155 99.95,46.155 100.384,46.59 U35_N.5@100.384,47.9
  Bottom Layer w0.254: U31_N.11@84.8,39 85.048,39.248 85.048,40.428 85.197,40.577 89.797,40.577 90.875,39.499 C204_N.1@90.875,38.482 ; v1(89.65,43.25) 89.675,43.275 98.667,43.275 99.615,44.223 99.615,44.927 R296_N.2@99.618,44.93 ; v1(98.368,46.275) 98.416,46.226 98.919,46.226 99.27,45.875 99.27,45.278 R296_N.2@99.618,44.93 ; R296_N.2@99.643,44.93 R296_N.2@99.618,44.93
10V_S3_GaN_L1: C229_L1.1 C232_L1.1 R306_L1.2 R310_L1.2 U36_L1.11 U40_L1.5 | length 27.2
  Top Layer w0.254: v1(52.842,135.373) 52.842,136.303 53.047,136.508 C232_L1.1@54.429,136.508 ; v1(53.222,145.422) 53.222,141.546 54.51,140.257 54.51,136.427 54.654,136.283 U40_L1.5@56.083,136.283 56.103,136.303 56.61,136.303 56.983,136.676 R310_L1.2@56.983,138.942
  Bottom Layer w0.254: U36_L1.11@52,151.7 53.544,151.7 53.824,151.42 53.824,146.025 v1(53.222,145.422) C229_L1.1@53.222,144.55 ; v1(52.842,135.373) 52.842,136.378 R306_L1.2@52.897,136.433
10V_S3_GaN_L2: C229_L2.1 C232_L2.1 R306_L2.2 R310_L2.2 U36_L2.11 U40_L2.5 | length 27.2
  Top Layer w0.254: v1(136.842,120.373) 136.842,121.303 137.047,121.508 C232_L2.1@138.429,121.508 ; v1(137.222,130.422) 137.222,126.546 138.51,125.257 138.51,121.427 138.654,121.283 U40_L2.5@140.083,121.283 140.103,121.303 140.61,121.303 140.983,121.676 R310_L2.2@140.983,123.942
  Bottom Layer w0.254: U36_L2.11@136,136.7 137.544,136.7 137.824,136.42 137.824,131.025 v1(137.222,130.422) C229_L2.1@137.222,129.55 ; v1(136.842,120.373) 136.842,121.378 R306_L2.2@136.897,121.433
